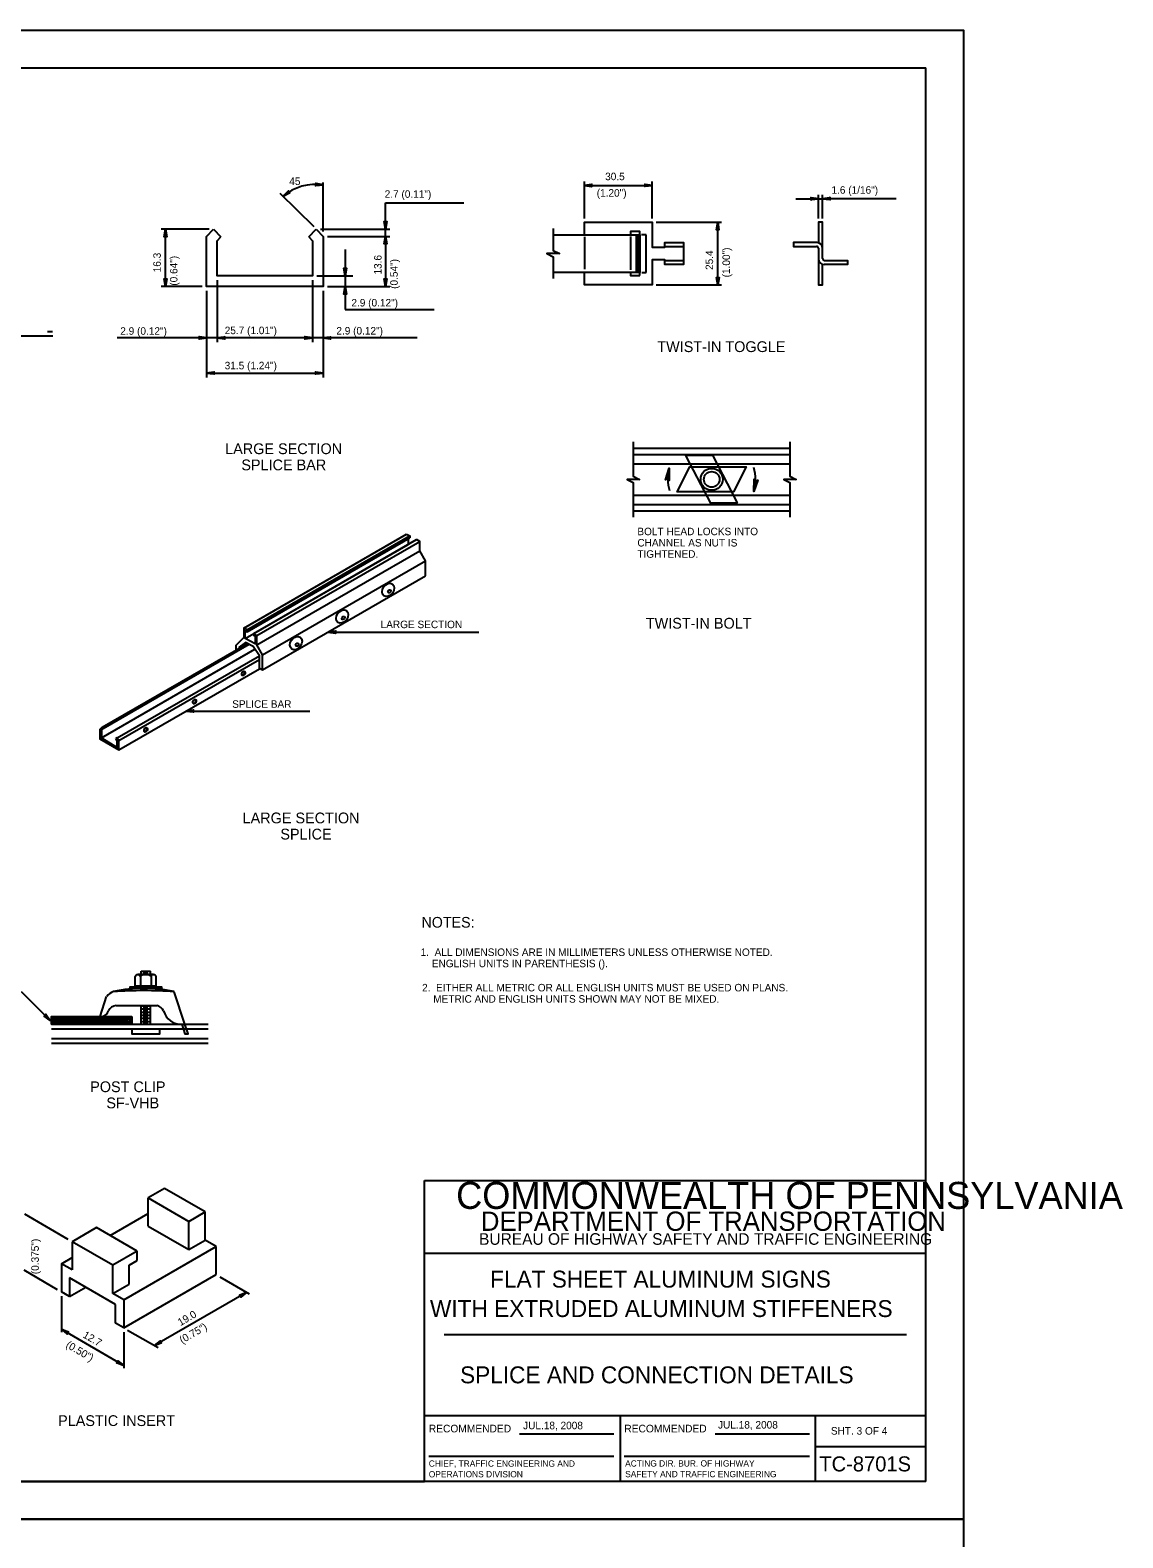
# Model space of a CAD drawing. Extents: x 650495 to 652241, y 298458 to 299646.
# Drawn here: x 651805 to 652241, y 299044 to 299646 of the extents above; entities that cross this region are included whole.
import ezdxf

# ---------------------------------------------------------------- set-up
doc = ezdxf.new("R2010")
doc.units = 0
for name, color, linetype in [('1', 7, 'Continuous'), ('2', 7, 'Continuous'), ('3', 7, 'Continuous'), ('Default', 7, 'Continuous'), ('PLT-BNDY', 7, 'Continuous')]:
    doc.layers.add(name, color=color, linetype=linetype)

# ---------------------------------------------------------------- blocks, each defined once
blk = doc.blocks.new('RARROW')
at = {"layer": '3'}
blk.add_lwpolyline([(-2.2695, 0.285), (-2.184875, 0.12075), (0, 0), (-2.2695, 0.285), (-2.38575, 0.384625), (0, 0), (-2.183125, -0.108), (-2.262875, -0.2705), (0, 0), (-2.38575, -0.379125), (-2.262875, -0.2705)], dxfattribs=at)

msp = doc.modelspace()

# ---------------------------------------------------------------- linework, layer by layer
at = {"layer": '1'}
for p, q in [((651376.31, 299630.63), (652162.31, 299630.63)), ((652162.31, 299066.63), (652162.31, 299630.63)), ((651962.31, 299066.63), (651962.31, 299186.63)), ((651962.31, 299186.63), (652162.31, 299186.63)), ((652162.31, 299157.63), (651962.31, 299157.63)), ((651970.06, 299125.31), (652154.56, 299125.31)), ((651962.31, 299093), (652162.31, 299093)), ((652040.31, 299093), (652040.31, 299066.63)), ((652118.19, 299066.63), (652118.19, 299093)), ((652000.24, 299085.57), (652037.87, 299085.57)), ((652078.24, 299085.57), (652115.87, 299085.57)), ((652118.19, 299080.63), (652162.31, 299080.63)), ((651963.99, 299076.68), (652037.87, 299076.68)), ((652041.99, 299076.68), (652115.87, 299076.68)), ((652162.31, 299066.63), (651376.31, 299066.63)), ((651376.31, 299066.63), (651962.31, 299066.63))]:
    msp.add_line(p, q, dxfattribs=at)
at = {"layer": '2'}
for p, q in [((651921.83, 299565.36), (651921.83, 299584.86)), ((652026.07, 299570.5), (652026.07, 299585.19)), ((652026.07, 299583.69), (652053.14, 299583.69)), ((652053.14, 299570.5), (652053.14, 299585.19)), ((651918.21, 299567.11), (651904.71, 299580.49)), ((652110.44, 299578.38), (652121.06, 299578.38)), ((652119.44, 299570.5), (652119.44, 299579.88)), ((652121.06, 299570.5), (652121.06, 299579.88)), ((652150.47, 299578.38), (652121.06, 299578.38)), ((651946.71, 299563.36), (651946.71, 299576.74)), ((651946.71, 299576.74), (651977.92, 299576.74)), ((651876.33, 299566.23), (651857.21, 299566.23)), ((651858.96, 299543.36), (651858.96, 299566.23)), ((651878.08, 299566.23), (651881.08, 299563.11)), ((651916.08, 299563.11), (651919.08, 299566.23)), ((651920.83, 299566.23), (651948.46, 299566.23)), ((652054.64, 299569), (652080.76, 299569)), ((652079.26, 299544), (652079.26, 299569)), ((651923.58, 299563.36), (651948.46, 299563.36)), ((651946.71, 299563.36), (651946.71, 299543.36)), ((652026.07, 299563.11), (652026.07, 299550.32)), ((652044.39, 299563.28), (652044.39, 299550.04)), ((652046.76, 299564), (652046.76, 299549)), ((652047.51, 299564), (652047.51, 299549)), ((652050.64, 299564), (652048.82, 299564)), ((652050.64, 299549), (652050.64, 299564)), ((652058.14, 299559.38), (652065.64, 299559.38)), ((651930.65, 299558.11), (651930.65, 299547.61)), ((652058.49, 299553.75), (652065.64, 299553.75)), ((652119.44, 299558.63), (652119.44, 299554.5)), ((651919.33, 299547.61), (651933.72, 299547.61)), ((651930.65, 299547.61), (651930.65, 299534.23)), ((652048.93, 299549), (652050.64, 299549)), ((651873.58, 299543.36), (651857.21, 299543.36)), ((651875.33, 299541.61), (651875.33, 299507.08)), ((651879.58, 299545.86), (651879.58, 299521.09)), ((651917.58, 299545.86), (651917.58, 299521.09)), ((651921.83, 299541.61), (651921.83, 299507.08)), ((651923.58, 299543.36), (651937.83, 299543.36)), ((651923.58, 299543.36), (651948.46, 299543.36)), ((652054.64, 299544), (652080.76, 299544)), ((651930.65, 299534.23), (651966.18, 299534.23)), ((651729.65, 299523.7), (651814, 299523.7)), ((651811.9, 299525.39), (651813.89, 299525.39)), ((651879.58, 299522.84), (651839.63, 299522.84)), ((651917.58, 299522.84), (651879.58, 299522.84)), ((651959.32, 299522.84), (651917.58, 299522.84)), ((651875.33, 299508.83), (651921.83, 299508.83)), ((652045.56, 299478.88), (652108.06, 299478.88)), ((652045.56, 299476.38), (652108.06, 299476.38)), ((652045.56, 299472.63), (652108.06, 299472.63)), ((652045.56, 299460.13), (652108.06, 299460.13)), ((652045.56, 299456.38), (652108.06, 299456.38)), ((652045.56, 299453.88), (652108.06, 299453.88)), ((651890.15, 299407.11), (651955.15, 299444.61)), ((651890.78, 299405.99), (651955.78, 299443.49)), ((651890.78, 299402.99), (651955.78, 299440.49)), ((651891.53, 299406.36), (651956.4, 299443.86)), ((651891.53, 299405.61), (651956.4, 299443.11)), ((651894.15, 299404.86), (651959.03, 299442.36)), ((651895.4, 299404.11), (651960.4, 299441.61)), ((651895.4, 299400.36), (651960.4, 299437.86)), ((651897.65, 299396.36), (651962.65, 299433.86)), ((651897.65, 299390.36), (651962.65, 299427.86)), ((651923.9, 299405.49), (651983.95, 299405.49)), ((651833.4, 299363.24), (651894.65, 299398.61)), ((651833.65, 299367.49), (651891.65, 299400.99)), ((651834.03, 299366.99), (651892.28, 299400.61)), ((651839.65, 299363.24), (651896.4, 299395.99)), ((651840.28, 299362.24), (651896.4, 299394.61)), ((651840.28, 299358.49), (651896.4, 299390.86)), ((651867.15, 299373.99), (651916.57, 299373.99)), ((651834.03, 299366.99), (651833.65, 299367.49)), ((651839.65, 299363.24), (651839.15, 299362.99)), ((651846.85, 299264.39), (651846.85, 299268.14)), ((651846.85, 299264.39), (651855.22, 299264.39)), ((651847.22, 299264.39), (651847.22, 299264.14)), ((651854.1, 299268.89), (651847.97, 299268.89)), ((651848.97, 299268.02), (651848.97, 299264.39)), ((651849.22, 299270.27), (651852.97, 299270.27)), ((651849.22, 299268.89), (651849.22, 299270.27)), ((651849.35, 299270.14), (651852.72, 299270.14)), ((651850.1, 299269.52), (651851.85, 299269.52)), ((651852.97, 299268.89), (651852.97, 299270.27)), ((651853.22, 299268.02), (651853.22, 299264.39)), ((651854.97, 299264.39), (651854.97, 299264.14)), ((651855.22, 299264.39), (651855.22, 299268.14)), ((651812.97, 299250.52), (651801.54, 299262.02)), ((651832.85, 299252.14), (651835.47, 299260.14)), ((651847.22, 299264.14), (651854.97, 299264.14)), ((651866.72, 299249.02), (651862.35, 299262.02)), ((651839.22, 299256.52), (651855.47, 299256.52)), ((651849.22, 299249.02), (651849.22, 299256.52)), ((651849.35, 299256.39), (651852.72, 299256.39)), ((651849.35, 299255.14), (651852.72, 299255.14)), ((651849.35, 299253.89), (651852.72, 299253.89)), ((651849.35, 299252.64), (651852.72, 299252.64)), ((651850.1, 299255.77), (651851.85, 299255.77)), ((651850.1, 299254.52), (651851.85, 299254.52)), ((651850.1, 299253.27), (651851.85, 299253.27)), ((651852.97, 299249.02), (651852.97, 299256.52)), ((651813.47, 299249.02), (651875.97, 299249.02)), ((651813.47, 299247.14), (651875.97, 299247.14)), ((651849.35, 299251.39), (651852.72, 299251.39)), ((651849.35, 299250.14), (651852.72, 299250.14)), ((651850.1, 299252.02), (651851.85, 299252.02)), ((651850.1, 299250.77), (651851.85, 299250.77)), ((651850.1, 299249.52), (651851.85, 299249.52)), ((651856.72, 299247.14), (651856.72, 299247.14)), ((651865.47, 299249.02), (651865.47, 299249.02)), ((651813.47, 299243.39), (651875.97, 299243.39)), ((651813.47, 299241.52), (651875.97, 299241.52)), ((651858.53, 299183.51), (651852.03, 299179.76)), ((651874.78, 299174.13), (651858.53, 299183.51)), ((651852.03, 299179.76), (651868.28, 299170.38)), ((651852.03, 299168.51), (651852.03, 299179.76)), ((651868.28, 299170.38), (651874.78, 299174.13)), ((651874.78, 299162.88), (651874.78, 299174.13)), ((651820.16, 299163.13), (651802.78, 299173.28)), ((651836.91, 299164.76), (651852.03, 299173.51)), ((651852.03, 299168.51), (651868.28, 299159.13)), ((651868.28, 299159.13), (651868.28, 299170.38)), ((651831.41, 299167.88), (651821.78, 299162.26)), ((651837.91, 299152.88), (651821.78, 299162.26)), ((651821.78, 299162.26), (651821.78, 299151.01)), ((651847.66, 299158.51), (651831.41, 299167.88)), ((651868.28, 299159.13), (651874.78, 299162.88)), ((651879.16, 299160.38), (651874.78, 299162.88)), ((651847.66, 299158.51), (651837.91, 299152.88)), ((651842.28, 299139.13), (651879.16, 299160.38)), ((651847.66, 299154.76), (651847.66, 299158.51)), ((651879.16, 299149.13), (651879.16, 299160.38)), ((651815.91, 299143.13), (651802.59, 299150.9)), ((651817.41, 299153.51), (651821.78, 299156.01)), ((651817.41, 299153.51), (651817.41, 299142.26)), ((651821.78, 299151.01), (651817.41, 299153.51)), ((651837.91, 299141.63), (651837.91, 299152.88)), ((651844.41, 299152.88), (651847.66, 299154.76)), ((651844.41, 299145.38), (651844.41, 299152.88)), ((651839.03, 299137.26), (651820.66, 299147.88)), ((651820.66, 299147.88), (651820.66, 299140.38)), ((651820.66, 299140.38), (651827.16, 299144.13)), ((651837.91, 299141.63), (651844.41, 299145.38)), ((651842.28, 299127.88), (651879.16, 299149.13)), ((651880.66, 299148.26), (651892.28, 299141.49)), ((651820.66, 299140.38), (651817.41, 299142.26)), ((651817.41, 299140.51), (651817.41, 299126.13)), ((651842.28, 299139.13), (651837.91, 299141.63)), ((651842.28, 299139.13), (651842.28, 299127.88)), ((651891.3, 299142.06), (651854.58, 299120.84)), ((651839.03, 299129.76), (651839.03, 299137.26)), ((651817.41, 299127.36), (651842.28, 299112.84)), ((651842.28, 299127.88), (651839.03, 299129.76)), ((651842.28, 299126.13), (651842.28, 299111.76)), ((651843.78, 299127.01), (651855.99, 299120.03))]:
    msp.add_line(p, q, dxfattribs=at)
for points in [[(651919.08, 299566.23), (651921.83, 299563.36), (651921.83, 299543.36), (651875.33, 299543.36), (651875.33, 299563.36), (651878.08, 299566.23)], [(652013.57, 299566.5), (652013.57, 299557.75), (652016.07, 299556.5), (652011.07, 299556.5), (652013.57, 299555.25), (652013.57, 299546.5)], [(652026.07, 299564), (652026.07, 299569), (652053.14, 299569), (652053.14, 299559), (652058.14, 299559), (652058.14, 299560.88), (652065.64, 299560.88), (652065.64, 299552.13), (652058.14, 299552.13), (652058.14, 299554), (652053.14, 299554), (652053.14, 299544), (652026.07, 299544), (652026.07, 299549)], [(652121.06, 299554.5), (652121.06, 299569), (652119.44, 299569), (652119.44, 299560.78)], [(651916.08, 299563.11), (651917.58, 299561.61), (651917.58, 299547.61), (651879.58, 299547.61), (651879.58, 299561.61), (651881.08, 299563.11)], [(652013.57, 299564), (652048.14, 299564), (652048.14, 299549), (652013.57, 299549)], [(652118.76, 299560.88), (652109.44, 299560.88), (652109.44, 299559.38), (652118.69, 299559.38)], [(652119.44, 299558.63), (652119.44, 299544), (652121.06, 299544), (652121.06, 299552.23)], [(652121.81, 299553.75), (652131.06, 299553.75), (652131.06, 299552.13), (652121.74, 299552.13)], [(652045.56, 299481.38), (652045.56, 299467.63), (652048.06, 299466.38), (652043.06, 299466.38), (652045.56, 299465.13), (652045.56, 299451.38)], [(652108.06, 299481.38), (652108.06, 299467.63), (652110.56, 299466.38), (652105.56, 299466.38), (652108.06, 299465.13), (652108.06, 299451.38)], [(652072.69, 299464.25), (652066.56, 299475.88), (652077.19, 299476), (652087.06, 299457), (652076.44, 299456.88), (652072.69, 299464.25)], [(652058.69, 299466.5), (652058.94, 299466.63), (652059.94, 299470.88), (652058.69, 299466.5), (652058.44, 299466.25), (652059.94, 299470.88), (652059.44, 299466.5), (652059.69, 299466.38), (652059.94, 299470.88), (652059.94, 299466), (652059.69, 299466.38)], [(652076.81, 299471.38), (652090.56, 299471.38), (652085.56, 299461.38), (652063.06, 299461.38), (652068.06, 299471.38), (652076.81, 299471.38)], [(652095.06, 299466), (652094.69, 299465.88), (652093.69, 299461.63), (652095.06, 299466), (652095.31, 299466.13), (652093.69, 299461.63), (652094.19, 299466), (652093.94, 299466.13), (652093.69, 299461.63), (652093.81, 299466.5), (652093.94, 299466.13)], [(651955.15, 299444.61), (651956.4, 299443.86), (651956.4, 299443.11)], [(651955.78, 299442.74), (651955.78, 299440.49)], [(651962.65, 299427.86), (651962.65, 299433.86), (651960.4, 299437.86), (651960.4, 299441.61), (651959.03, 299442.36)], [(651896.4, 299391.11), (651897.65, 299390.36), (651897.65, 299396.36), (651895.4, 299400.36), (651895.4, 299404.11), (651894.15, 299404.86), (651894.15, 299404.11), (651894.78, 299403.74), (651894.78, 299400.74), (651890.78, 299402.99), (651890.78, 299405.99), (651891.53, 299405.61), (651891.53, 299406.36), (651890.15, 299407.11), (651890.15, 299403.36), (651887.03, 299400.11), (651887.03, 299398.24)], [(651896.4, 299391.11), (651896.4, 299395.99), (651893.9, 299399.74), (651890.9, 299401.36), (651888.28, 299399.49), (651888.28, 299398.99)], [(651833.65, 299367.49), (651832.78, 299366.61), (651832.78, 299362.86), (651840.28, 299358.49), (651840.28, 299362.24), (651839.65, 299363.24)], [(651834.03, 299366.99), (651833.4, 299366.36), (651833.4, 299363.24), (651839.65, 299359.49), (651839.65, 299361.99), (651839.15, 299362.99)], [(651813.72, 299251.52), (651844.97, 299251.52), (651844.97, 299249.64), (651813.72, 299249.39), (651813.72, 299251.14), (651844.47, 299251.14), (651844.6, 299250.14), (651814.35, 299249.64), (651814.47, 299250.64), (651843.72, 299250.64), (651843.72, 299250.52), (651814.6, 299250.14)], [(651845.47, 299247.14), (651845.47, 299245.27), (651856.72, 299245.27), (651856.72, 299247.14)], [(651865.47, 299249.02), (651866.72, 299245.27), (651867.97, 299245.27), (651866.72, 299249.02)]]:
    msp.add_lwpolyline(points, dxfattribs=at)
for points in [[(652048.14, 299564), (652048.14, 299565.25), (652044.39, 299565.25), (652044.39, 299564)], [(652048.14, 299547.75), (652048.14, 299549), (652044.39, 299549), (652044.39, 299547.75)], [(651844.85, 299263.27), (651844.85, 299263.89), (651857.35, 299263.89), (651857.35, 299263.27)], [(651845.47, 299252.14), (651845.47, 299249.02), (651813.47, 299249.02), (651813.47, 299252.14)]]:
    msp.add_lwpolyline(points, close=True, dxfattribs=at)
for radius in [4.38, 3.12]:
    msp.add_circle((652076.85, 299466.42), radius, dxfattribs=at)
for centre, radius, start, end in [((651918.83, 299563.94), 20.14, 81.42065, 130.10106), ((652118.69, 299558.63), 0.75, 0, 90), ((652118.76, 299558.58), 2.3, 0, 90), ((652121.74, 299554.43), 2.3, 180, 270), ((652121.81, 299554.5), 0.75, 180, 270), ((652076.85, 299466.42), 17.49, 165.2574, 194.94011), ((652076.85, 299466.42), 17.49, 344.07384, 15.48813), ((651848.03, 299268.76), 0.113, 90, 180), ((651854.1, 299268.76), 0.113, 0, 90), ((651839.31, 299257.56), 4.6, 103.47229, 145.70272), ((651850.31, 299206.21), 57.12, 77.80349, 102.1965), ((651850.31, 299087.5), 174.95, 86.04462, 93.95539), ((651832.89, 299255.49), 3.48, 282.55259, 342.47234), ((651839.61, 299252.69), 3.82, 95.78592, 152.80494), ((651854.51, 299252.45), 4.15, 26.88629, 76.60858), ((651865.12, 299256.12), 7.13, 194.52183, 272.8108)]:
    msp.add_arc(centre, radius, start, end, dxfattribs=at)
for centre, major_axis, ratio in [((651947.81, 299422.32), (1.7, 2.34), 0.738176), ((651948.29, 299421.73), (0.425, 0.585), 0.738176), ((651929.41, 299411.69), (1.7, 2.34), 0.738176), ((651929.89, 299411.11), (0.425, 0.585), 0.738176), ((651911, 299401.07), (1.7, 2.34), 0.738176), ((651911.48, 299400.48), (0.425, 0.585), 0.738176), ((651890.05, 299389.01), (0.443, 0.822), 0.636755), ((651870.56, 299377.76), (0.443, 0.822), 0.636755), ((651851.07, 299366.51), (0.443, 0.822), 0.636755)]:
    msp.add_ellipse(centre, major_axis=major_axis, ratio=ratio, dxfattribs=at)
for centre, major_axis, ratio, start_param, end_param in [((651889.88, 299389.1), (0.443, 0.822), 0.636755, 3.280378, 6.105665), ((651870.4, 299377.85), (0.443, 0.822), 0.636755, 3.280378, 6.105665), ((651850.91, 299366.6), (0.443, 0.822), 0.636755, 3.280378, 6.105665), ((651847.91, 299268.04), (1.03, 0.01), 0.679853, 0, 3.035161), ((651851.06, 299268.06), (-2.12, -0.01), 0.335964, 3.141593, 6.283185), ((651854.21, 299268.06), (-1.03, 0.01), 0.679853, 3.248025, 6.283185)]:
    msp.add_ellipse(centre, major_axis=major_axis, ratio=ratio, start_param=start_param, end_param=end_param, dxfattribs=at)
at = {"layer": 'PLT-BNDY'}
for points in [[(651336.31, 299645.63), (652177.31, 299645.63), (652177.31, 299051.63), (651336.31, 299051.63)], [(651336.31, 299051.63), (652177.31, 299051.63), (652177.31, 298457.63), (651336.31, 298457.63)]]:
    msp.add_lwpolyline(points, close=True, dxfattribs=at)

# ---------------------------------------------------------------- block references
at = {"layer": '2'}
for p, xscale, yscale, rotation in [((651921.83, 299583.86), 1.257434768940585, 1.3092961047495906, -4.1307990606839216), ((652026.07, 299583.69), 1.2574347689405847, 1.3092961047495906, 180), ((651905.86, 299579.35), 1.2574347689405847, 1.3092961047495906, -143.18293648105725), ((652121.06, 299578.38), 1.2574347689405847, 1.3092961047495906, 180), ((651858.96, 299566.23), 1.2574347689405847, 1.3092961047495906, 89.99999999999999), ((651946.71, 299566.23), 1.2574347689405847, 1.3092961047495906, -90.00000000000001), ((652079.26, 299569), 1.2574347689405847, 1.3092961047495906, 89.99999999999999), ((651946.71, 299563.36), 1.2574347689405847, 1.3092961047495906, 89.99999999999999), ((651930.65, 299547.61), 1.2574347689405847, 1.3092961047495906, -90.00000000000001), ((652079.26, 299544), 1.2574347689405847, 1.3092961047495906, -90.00000000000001), ((651858.96, 299543.36), 1.2574347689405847, 1.3092961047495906, -90.00000000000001), ((651930.65, 299543.36), 1.2574347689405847, 1.3092961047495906, 89.99999999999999), ((651946.71, 299543.36), 1.2574347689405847, 1.3092961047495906, -90.00000000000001), ((651879.58, 299522.84), 1.2574347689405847, 1.3092961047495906, 180), ((651921.83, 299522.84), 1.2574347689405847, 1.3092961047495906, 180), ((651875.33, 299508.83), 1.2574347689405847, 1.3092961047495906, 180), ((651923.9, 299405.49), 1.2574347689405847, 1.3092961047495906, 180), ((651867.15, 299373.99), 1.2574347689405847, 1.3092961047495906, 180), ((651812.97, 299250.52), 1.2574347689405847, 1.3092961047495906, -44.8426609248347), ((651812.97, 299250.52), 0.0018861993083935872, 0.001963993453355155, -46.50743575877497), ((651891.3, 299142.06), 1.2574347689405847, 1.3092961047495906, 30.434578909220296), ((651817.41, 299127.35), 1.2574347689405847, 1.3092961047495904, 149.64469446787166), ((651854.58, 299120.84), 1.2574347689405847, 1.3092961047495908, -149.86157797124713), ((651842.28, 299112.84), 1.2574347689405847, 1.3092961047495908, -30.0868603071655)]:
    msp.add_blockref('RARROW', p, dxfattribs=dict(at, xscale=xscale, yscale=yscale, rotation=rotation))
at = {"layer": '2', "xscale": 1.2574347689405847, "yscale": 1.3092961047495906}
for p in [(652053.14, 299583.69), (652119.44, 299578.38), (651875.33, 299522.84), (651917.58, 299522.84), (651921.83, 299508.83)]:
    msp.add_blockref('RARROW', p, dxfattribs=at)

# ---------------------------------------------------------------- texts
at = {"layer": '1'}
for s, height, p in [('COMMONWEALTH OF PENNSYLVANIA', 10.7828, (651974.9, 299175.36)), ('DEPARTMENT OF TRANSPORTATION', 7.6837, (651984.76, 299166.61)), ('BUREAU OF HIGHWAY SAFETY AND TRAFFIC ENGINEERING', 4.6253, (651984.04, 299161.04)), ('FLAT SHEET ALUMINUM SIGNS', 6.75, (651988.47, 299143.97)), ('WITH EXTRUDED ALUMINUM STIFFENERS', 6.75, (651964.47, 299132.22)), ('SPLICE AND CONNECTION DETAILS', 6.75, (651976.47, 299105.78)), ('RECOMMENDED', 3.048, (651963.99, 299086.2)), ('RECOMMENDED', 3.048, (652041.99, 299086.2)), ('SHT. 3 OF 4', 3, (652124.4, 299085.31)), ('CHIEF, TRAFFIC ENGINEERING AND', 2.5, (651963.99, 299072.51)), ('TC-8701S', 6, (652119.79, 299070.63)), ('OPERATIONS DIVISION', 2.5, (651963.99, 299068.26))]:
    msp.add_text(s, height=height, dxfattribs=at).set_placement(p)
at = {"layer": '2'}
for s, height, p in [('45', 2.999, (651908.33, 299583.86)), ('30.5', 3, (652034.34, 299585.76)), ('1.6 (1/16")', 3, (652124.63, 299580.37)), ('2.7 (0.11")', 3, (651946.39, 299578.74)), ('(1.20")', 3, (652030.98, 299579.2)), ('2.9 (0.12")', 3, (651933.12, 299535.39)), ('2.9 (0.12")', 3, (651840.92, 299524.1)), ('25.7 (1.01")', 3, (651882.58, 299524.34)), ('2.9 (0.12")', 3, (651927.12, 299524.2)), ('TWIST-IN TOGGLE', 4.3, (652055.15, 299517.2)), ('31.5 (1.24")', 3, (651882.57, 299510.32)), ('LARGE SECTION', 4.3, (651882.76, 299476.48)), ('SPLICE BAR', 4.3, (651889.21, 299470.03)), ('BOLT HEAD LOCKS INTO', 3, (652047.19, 299444.13)), ('CHANNEL AS NUT IS', 3, (652047.19, 299439.63)), ('TIGHTENED.', 3, (652047.19, 299435.13)), ('LARGE SECTION', 3, (651944.77, 299407.05)), ('TWIST-IN BOLT', 4.3, (652050.57, 299406.86)), ('SPLICE BAR', 3, (651885.57, 299375.27)), ('LARGE SECTION', 4.3, (651889.71, 299329.18)), ('SPLICE', 4.3, (651904.78, 299322.73)), ('NOTES:', 4.25, (651961.08, 299287.58)), ('1.  ALL DIMENSIONS ARE IN MILLIMETERS UNLESS OTHERWISE NOTED.', 3, (651960.74, 299276.27)), ('    ENGLISH UNITS IN PARENTHESIS ().', 3, (651960.74, 299271.77)), ('2.  EITHER ALL METRIC OR ALL ENGLISH UNITS MUST BE USED ON PLANS.', 3, (651961.31, 299262.13)), ('    METRIC AND ENGLISH UNITS SHOWN MAY NOT BE MIXED.', 3, (651961.31, 299257.63)), ('POST CLIP', 4.3, (651828.91, 299221.94)), ('SF-VHB', 4.3, (651835.36, 299215.49)), ('PLASTIC INSERT', 4.3, (651816.11, 299088.74)), ('JUL.18, 2008', 3, (652001.61, 299087.45)), ('JUL.18, 2008', 3, (652079.37, 299087.72))]:
    msp.add_text(s, height=height, dxfattribs=at).set_placement(p)
for s, rotation, p in [('16.3', 90, (651857.08, 299549.01)), (' (0.64")', 90, (651863.73, 299542.57)), ('13.6', 90, (651945.15, 299548.11)), (' (0.54")', 90, (651951.61, 299541.3)), ('25.4 ', 90, (652077.41, 299549.95)), ('(1.00")', 90, (652084.14, 299547)), ('(0.375")', 90, (651808.42, 299149.32)), ('19.0', 30.02706, (651864.91, 299128.54)), ('12.7', 329.74364, (651825.69, 299124.26)), ('(0.75")', 30.02706, (651865.59, 299121.5)), ('(0.50")', 329.74364, (651818.9, 299120.32))]:
    msp.add_text(s, height=3, rotation=rotation, dxfattribs=at).set_placement(p)
at = {"layer": 'Default'}
for s, p in [('ACTING DIR. BUR. OF HIGHWAY', (652042.32, 299072.57)), ('SAFETY AND TRAFFIC ENGINEERING', (652042.32, 299068.32))]:
    msp.add_text(s, height=2.5, dxfattribs=at).set_placement(p)

doc.saveas('drawing.dxf')
